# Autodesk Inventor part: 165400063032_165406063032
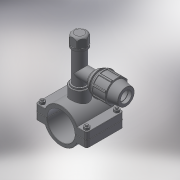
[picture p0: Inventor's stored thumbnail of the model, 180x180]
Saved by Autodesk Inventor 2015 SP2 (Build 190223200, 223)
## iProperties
Created: 2017-05
Part Number: 165400063032_165406063032
Material: Generic
Description: PLASSON TAPPER FOR PE+PVC PIPE 63-32
Document SubType Name: Modeling
Designer: KIM
Density: 1 g/cm^3
Appearance: Default
Author: KIM
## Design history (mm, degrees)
derived "16540.ipt"
feature "Solid1::16540.ipt"
feature "Solid2::16540.ipt"
tag "TaggingFeature1"
body "Solid1"
other parameters: "d0" = 78.75, "d1" = 116, "d2" = 31.5, "d3" = 63, "d4" = 84, "d5" = 0, "d6" = 5.8, "d7" = 116, "d8" = 0.1, "d10" = 0, "d11" = 0.63, "d14" = 50.6376, "d20" = 0.63, "d23" = 0.63, "d37" = 8, "d38" = 39.5, "d39" = 0, "d40" = 3, "d41" = 5, "d42" = 0, "d43" = 6, "d44" = 3, "d45" = 0, "d46" = 0.63, "d51" = 66, "d52" = 38.952, "d53" = 25, "d54" = 0, "d55" = 32, "d57" = 0, "d58" = 68.04, "d60" = 0, "d63" = 8, "d66" = 68, "d67" = 32, "d68" = 9.08333, "d69" = 21.8, "d70" = 64, "d71" = 48, "d72" = 1.55714, "d73" = 51.2, "d74" = 120 deg, "d75" = 48, "d76" = 10 deg, "d77" = 57.6, "d78" = 32.7, "d79" = 71, "d80" = 25.6, "d81" = 109, "d82" = 7.1, "d87" = 15.57143, "d90" = 59.52, "d91" = 35 deg, "d92" = 17.5 deg, "d94" = 0, "d96" = 360 deg, "d98" = 0.64, "d99" = 78.1, "d100" = 35.0568, "d101" = 135 deg, "d102" = 1.28, "d105" = 3.2, "d106" = 0, "d107" = 0.1, "d108" = 35.0568, "d109" = 42.8472, "d111" = 26, "d112" = 6.5, "d113" = 3.63333, "d116" = 0, "d117" = 38, "d118" = 21.8, "d119" = 0, "d122" = 57, "d_" = 63, "B_" = 32, "G_" = 38.952, "A_" = 66, "L_" = 116, "L_1" = 84, "l_2" = 25, "d_1" = 32, "E_" = 64, "l_" = 71, "H_" = 109, "H_1" = 57
